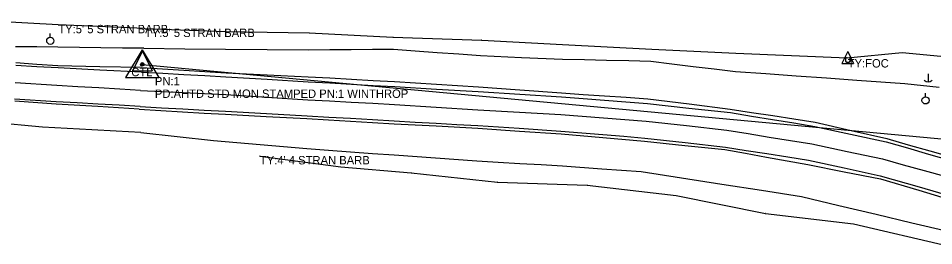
# Model space of a CAD drawing. Extents: x 592653 to 596268, y 1744647 to 1746025.
# Drawn here: x 593199 to 593746, y 1745827 to 1745963 of the extents above; entities that cross this region are included whole.
import ezdxf

# ---------------------------------------------------------------- set-up
doc = ezdxf.new("R2010")
doc.units = 0
for name, color, linetype in [('Default', 7, 'Continuous'), ('S_CAL_CORNER', 7, 'Continuous'), ('S_DITCHLINE', 7, 'Continuous'), ('S_EDGE_PAVEMENT', 7, 'Continuous'), ('S_FENCE', 7, 'Continuous'), ('S_FENCE_ANNOT', 7, 'Continuous'), ('S_MSC_PT_SYM', 7, 'Continuous'), ('S_PAVEMENT_CROWN', 7, 'Continuous'), ('S_PRIMARY_CTL', 7, 'Continuous'), ('S_PRIMARY_CTL_ANNOT', 7, 'Continuous'), ('S_SHOULDER', 7, 'Continuous'), ('S_UTILITY_POLE', 7, 'Continuous'), ('S_UTILITY_POLE_ANNOT', 7, 'Continuous')]:
    doc.layers.add(name, color=color, linetype=linetype)

msp = doc.modelspace()

# ---------------------------------------------------------------- linework, layer by layer
at = {"layer": 'Default'}
msp.add_line((593273.37, 1745935.37), (593756.49, 1745890.31), dxfattribs=at)
at = {"layer": 'S_CAL_CORNER'}
for p, q in [((593273.46, 1745943.35), (593267.58, 1745931.53)), ((593273.46, 1745943.35), (593279.27, 1745931.53)), ((593267.58, 1745931.53), (593279.27, 1745931.53))]:
    msp.add_line(p, q, dxfattribs=at)
at = {"layer": 'S_DITCHLINE'}
for points in [[(593223.04, 1745945.61), (593210.37, 1745945.77), (593197.7, 1745945.94)], [(593274.32, 1745944.97), (593261.5, 1745945.13), (593248.68, 1745945.29), (593235.86, 1745945.45), (593223.04, 1745945.61)], [(593274.32, 1745944.97), (593298.68, 1745944.69), (593323.04, 1745944.4), (593347.86, 1745944.27), (593372.68, 1745944.14), (593385.33, 1745944.24), (593397.98, 1745944.33), (593410.63, 1745944.43), (593423.27, 1745944.52), (593436.26, 1745943.54), (593449.25, 1745942.55), (593462.23, 1745941.57), (593475.22, 1745940.58), (593499.66, 1745939.55), (593524.11, 1745938.53), (593537.27, 1745938.21), (593550.43, 1745937.9), (593563.58, 1745937.59), (593576.74, 1745937.28), (593589.39, 1745935.73), (593602.03, 1745934.19), (593614.67, 1745932.64), (593627.31, 1745931.1), (593645.43, 1745929.83), (593663.54, 1745928.55), (593681.66, 1745927.28), (593699.77, 1745926.01), (593714.01, 1745924.97), (593728.26, 1745923.93), (593748.84, 1745921.72)], [(593213.86, 1745897.88), (593201.1, 1745899.09), (593188.35, 1745900.29)], [(593272.53, 1745894.74), (593257.86, 1745895.53), (593243.19, 1745896.31), (593228.52, 1745897.1), (593213.86, 1745897.88)], [(593272.53, 1745894.74), (593294.16, 1745892.32), (593315.79, 1745889.9), (593329.71, 1745888.72), (593343.64, 1745887.54), (593357.56, 1745886.36), (593371.48, 1745885.18), (593384.53, 1745884.21), (593397.58, 1745883.24), (593410.63, 1745882.27), (593423.68, 1745881.3), (593448.35, 1745879.55), (593473.02, 1745877.81), (593485.79, 1745877.05), (593498.56, 1745876.3), (593511.33, 1745875.54), (593524.1, 1745874.78), (593547.53, 1745873.07), (593570.95, 1745871.35), (593595.05, 1745867.64), (593619.14, 1745863.92), (593642.89, 1745860.25), (593666.64, 1745856.57), (593688.92, 1745851.23), (593711.19, 1745845.89), (593732.61, 1745840.86), (593754.04, 1745835.83)]]:
    msp.add_lwpolyline(points, dxfattribs=at)
at = {"layer": 'S_EDGE_PAVEMENT'}
for points in [[(593223.1, 1745933.25), (593210.51, 1745933.97), (593197.92, 1745934.69)], [(593272.95, 1745930.7), (593248.02, 1745931.97), (593223.1, 1745933.25)], [(593272.95, 1745930.7), (593285.53, 1745930.03), (593298.11, 1745929.36), (593310.7, 1745928.69), (593323.28, 1745928.02), (593347.77, 1745926.53), (593372.26, 1745925.05), (593385.21, 1745924.32), (593398.16, 1745923.59), (593411.11, 1745922.86), (593424.06, 1745922.13), (593448.95, 1745920.64), (593473.84, 1745919.16), (593498.68, 1745917.6), (593523.53, 1745916.04), (593536.32, 1745915.02), (593549.11, 1745914), (593561.91, 1745912.98), (593574.7, 1745911.97), (593599.47, 1745909.29), (593624.24, 1745906.62), (593636.83, 1745904.55), (593649.43, 1745902.49), (593662.02, 1745900.43), (593674.62, 1745898.36), (593695.91, 1745893.73), (593717.2, 1745889.09), (593729.84, 1745885.47), (593742.48, 1745881.85), (593755.13, 1745878.23)], [(593221.91, 1745913.07), (593197.1, 1745914.61)], [(593272.1, 1745910.21), (593259.55, 1745910.93), (593247.01, 1745911.64), (593234.46, 1745912.35), (593221.91, 1745913.07)], [(593272.1, 1745910.21), (593284.84, 1745909.51), (593297.58, 1745908.8), (593310.32, 1745908.09), (593323.06, 1745907.38), (593347.37, 1745906.04), (593371.68, 1745904.69), (593384.67, 1745903.94), (593397.67, 1745903.19), (593410.67, 1745902.43), (593423.66, 1745901.68), (593436.15, 1745900.98), (593448.63, 1745900.27), (593461.12, 1745899.57), (593473.6, 1745898.87), (593498.3, 1745897.21), (593523.01, 1745895.56), (593535.58, 1745894.53), (593548.15, 1745893.5), (593560.72, 1745892.46), (593573.29, 1745891.43), (593597.32, 1745888.72), (593621.35, 1745886.01), (593633.72, 1745884.06), (593646.08, 1745882.1), (593658.45, 1745880.15), (593670.82, 1745878.19), (593692.18, 1745873.53), (593713.55, 1745868.86), (593736.79, 1745862.21), (593760.04, 1745855.57)]]:
    msp.add_lwpolyline(points, dxfattribs=at)
at = {"layer": 'S_FENCE'}
for p, q in [((593223.26, 1745958.93), (593151.46, 1745962.87)), ((593274.91, 1745956.71), (593223.26, 1745958.93)), ((593274.91, 1745956.71), (593322.8, 1745954.94)), ((593322.8, 1745954.94), (593373.02, 1745954.18)), ((593373.02, 1745954.18), (593422.8, 1745951.7)), ((593422.8, 1745951.7), (593475.88, 1745949.73)), ((593475.88, 1745949.73), (593524.1, 1745947.23)), ((593524.1, 1745947.23), (593577.36, 1745944.46)), ((593577.36, 1745944.46), (593627.49, 1745942.11)), ((593627.49, 1745942.11), (593693.85, 1745939.24)), ((593693.85, 1745939.24), (593726.74, 1745942.49)), ((593726.74, 1745942.49), (593766.83, 1745938.65)), ((593343.52, 1745880.68), (593391.82, 1745874.16)), ((593391.82, 1745874.16), (593433.76, 1745870.7)), ((593433.76, 1745870.7), (593485.22, 1745865.01)), ((593485.22, 1745865.01), (593538.81, 1745863.36)), ((593538.81, 1745863.36), (593591.91, 1745857.11)), ((593591.91, 1745857.11), (593645.14, 1745846.3)), ((593645.14, 1745846.3), (593697.66, 1745840.19)), ((593697.66, 1745840.19), (593753.98, 1745827.15))]:
    msp.add_line(p, q, dxfattribs=at)
at = {"layer": 'S_MSC_PT_SYM'}
for points in [[(593223.26, 1745958.93), (593223.26, 1745958.98), (593223.26, 1745958.93), (593223.21, 1745958.93), (593223.26, 1745958.93), (593223.26, 1745958.88), (593223.26, 1745958.93), (593223.31, 1745958.93)], [(593274.91, 1745956.71), (593274.91, 1745956.76), (593274.91, 1745956.71), (593274.86, 1745956.71), (593274.91, 1745956.71), (593274.91, 1745956.66), (593274.91, 1745956.71), (593274.96, 1745956.71)], [(593322.8, 1745954.94), (593322.8, 1745954.99), (593322.8, 1745954.94), (593322.75, 1745954.94), (593322.8, 1745954.94), (593322.8, 1745954.89), (593322.8, 1745954.94), (593322.85, 1745954.94)], [(593373.02, 1745954.18), (593373.02, 1745954.23), (593373.02, 1745954.18), (593372.97, 1745954.18), (593373.02, 1745954.18), (593373.02, 1745954.13), (593373.02, 1745954.18), (593373.07, 1745954.18)], [(593422.8, 1745951.7), (593422.8, 1745951.75), (593422.8, 1745951.7), (593422.75, 1745951.7), (593422.8, 1745951.7), (593422.8, 1745951.65), (593422.8, 1745951.7), (593422.85, 1745951.7)], [(593475.88, 1745949.73), (593475.88, 1745949.78), (593475.88, 1745949.73), (593475.83, 1745949.73), (593475.88, 1745949.73), (593475.88, 1745949.68), (593475.88, 1745949.73), (593475.93, 1745949.73)], [(593524.1, 1745947.23), (593524.1, 1745947.28), (593524.1, 1745947.23), (593524.05, 1745947.23), (593524.1, 1745947.23), (593524.1, 1745947.18), (593524.1, 1745947.23), (593524.15, 1745947.23)], [(593577.36, 1745944.46), (593577.36, 1745944.51), (593577.36, 1745944.46), (593577.31, 1745944.46), (593577.36, 1745944.46), (593577.36, 1745944.41), (593577.36, 1745944.46), (593577.41, 1745944.46)], [(593627.49, 1745942.11), (593627.49, 1745942.16), (593627.49, 1745942.11), (593627.44, 1745942.11), (593627.49, 1745942.11), (593627.49, 1745942.06), (593627.49, 1745942.11), (593627.54, 1745942.11)], [(593726.74, 1745942.49), (593726.74, 1745942.54), (593726.74, 1745942.49), (593726.69, 1745942.49), (593726.74, 1745942.49), (593726.74, 1745942.44), (593726.74, 1745942.49), (593726.79, 1745942.49)], [(593693.85, 1745939.24), (593693.85, 1745939.29), (593693.85, 1745939.24), (593693.8, 1745939.24), (593693.85, 1745939.24), (593693.85, 1745939.19), (593693.85, 1745939.24), (593693.9, 1745939.24)], [(593343.52, 1745880.68), (593343.52, 1745880.73), (593343.52, 1745880.68), (593343.47, 1745880.68), (593343.52, 1745880.68), (593343.52, 1745880.63), (593343.52, 1745880.68), (593343.57, 1745880.68)], [(593391.82, 1745874.16), (593391.82, 1745874.21), (593391.82, 1745874.16), (593391.77, 1745874.16), (593391.82, 1745874.16), (593391.82, 1745874.11), (593391.82, 1745874.16), (593391.87, 1745874.16)], [(593433.76, 1745870.7), (593433.76, 1745870.75), (593433.76, 1745870.7), (593433.71, 1745870.7), (593433.76, 1745870.7), (593433.76, 1745870.65), (593433.76, 1745870.7), (593433.81, 1745870.7)], [(593485.22, 1745865.01), (593485.22, 1745865.06), (593485.22, 1745865.01), (593485.17, 1745865.01), (593485.22, 1745865.01), (593485.22, 1745864.96), (593485.22, 1745865.01), (593485.27, 1745865.01)], [(593538.81, 1745863.36), (593538.81, 1745863.41), (593538.81, 1745863.36), (593538.76, 1745863.36), (593538.81, 1745863.36), (593538.81, 1745863.31), (593538.81, 1745863.36), (593538.86, 1745863.36)], [(593591.91, 1745857.11), (593591.91, 1745857.16), (593591.91, 1745857.11), (593591.86, 1745857.11), (593591.91, 1745857.11), (593591.91, 1745857.06), (593591.91, 1745857.11), (593591.96, 1745857.11)], [(593645.14, 1745846.3), (593645.14, 1745846.35), (593645.14, 1745846.3), (593645.09, 1745846.3), (593645.14, 1745846.3), (593645.14, 1745846.25), (593645.14, 1745846.3), (593645.19, 1745846.3)], [(593697.66, 1745840.19), (593697.66, 1745840.24), (593697.66, 1745840.19), (593697.61, 1745840.19), (593697.66, 1745840.19), (593697.66, 1745840.14), (593697.66, 1745840.19), (593697.71, 1745840.19)]]:
    msp.add_lwpolyline(points, dxfattribs=at)
at = {"layer": 'S_PAVEMENT_CROWN'}
for points in [[(593222.38, 1745922.77), (593197.56, 1745924.28)], [(593272.36, 1745919.83), (593259.87, 1745920.56), (593247.37, 1745921.3), (593234.88, 1745922.03), (593222.38, 1745922.77)], [(593272.36, 1745919.83), (593285.06, 1745919.21), (593297.76, 1745918.6), (593310.46, 1745917.99), (593323.15, 1745917.38), (593347.61, 1745915.83), (593372.07, 1745914.29), (593384.99, 1745913.59), (593397.91, 1745912.89), (593410.83, 1745912.19), (593423.75, 1745911.48), (593448.68, 1745909.9), (593473.6, 1745908.33), (593498.37, 1745906.93), (593523.14, 1745905.54), (593535.86, 1745904.53), (593548.57, 1745903.53), (593561.29, 1745902.52), (593574, 1745901.51), (593598.05, 1745898.81), (593622.11, 1745896.11), (593634.77, 1745894.07), (593647.44, 1745892.02), (593660.11, 1745889.98), (593672.77, 1745887.94), (593693.86, 1745883.42), (593714.94, 1745878.91), (593727.36, 1745875.5), (593739.78, 1745872.08), (593752.2, 1745868.67)]]:
    msp.add_lwpolyline(points, dxfattribs=at)
at = {"layer": 'S_PRIMARY_CTL'}
for p, q in [((593273.37, 1745944.07), (593263.34, 1745927.55)), ((593273.37, 1745944.07), (593263.34, 1745927.55)), ((593273.37, 1745944.07), (593283.19, 1745927.55)), ((593273.37, 1745944.07), (593283.19, 1745927.55)), ((593263.34, 1745927.55), (593283.19, 1745927.55)), ((593263.34, 1745927.55), (593283.19, 1745927.55))]:
    msp.add_line(p, q, dxfattribs=at)
for radius in [1.04, 1.04, 0.609, 0.609, 0.344, 0.344]:
    msp.add_circle((593273.37, 1745935.37), radius, dxfattribs=at)
at = {"layer": 'S_SHOULDER'}
for points in [[(593223.02, 1745934.5), (593210.42, 1745935.35), (593197.82, 1745936.2)], [(593272.84, 1745933.47), (593247.93, 1745933.98), (593223.02, 1745934.5)], [(593272.84, 1745933.47), (593285.46, 1745932.71), (593298.08, 1745931.95), (593310.69, 1745931.18), (593323.31, 1745930.42), (593347.83, 1745929.21), (593372.35, 1745928), (593385.25, 1745927.28), (593398.14, 1745926.56), (593411.04, 1745925.83), (593423.94, 1745925.11), (593436.44, 1745924.31), (593448.94, 1745923.52), (593461.44, 1745922.72), (593473.94, 1745921.92), (593498.7, 1745920.13), (593523.45, 1745918.34), (593536.33, 1745917.47), (593549.21, 1745916.59), (593562.1, 1745915.72), (593574.98, 1745914.85), (593599.59, 1745911.76), (593624.2, 1745908.67), (593636.86, 1745906.72), (593649.52, 1745904.77), (593662.18, 1745902.82), (593674.84, 1745900.88), (593696.23, 1745895.98), (593717.62, 1745891.08), (593730.4, 1745887.44), (593743.17, 1745883.79), (593755.94, 1745880.14)], [(593221.99, 1745911.68), (593197.4, 1745913.32)], [(593271.56, 1745908.65), (593246.78, 1745910.17), (593221.99, 1745911.68)], [(593271.56, 1745908.65), (593284.43, 1745907.88), (593297.31, 1745907.11), (593310.18, 1745906.33), (593323.05, 1745905.56), (593347.28, 1745904.27), (593371.51, 1745902.99), (593384.56, 1745902.23), (593397.62, 1745901.46), (593410.68, 1745900.7), (593423.74, 1745899.94), (593448.63, 1745898.6), (593473.52, 1745897.27), (593498.41, 1745895.55), (593523.3, 1745893.82), (593548.19, 1745891.66), (593573.08, 1745889.51), (593597, 1745887.03), (593620.92, 1745884.56), (593633.31, 1745882.31), (593645.7, 1745880.06), (593658.08, 1745877.81), (593670.47, 1745875.56), (593692.17, 1745871.33), (593713.86, 1745867.1), (593736.68, 1745860.22), (593759.5, 1745853.33)]]:
    msp.add_lwpolyline(points, dxfattribs=at)
at = {"layer": 'S_UTILITY_POLE'}
for p, q in [((593218.33, 1745951.6), (593218.33, 1745953.71)), ((593694.26, 1745943.04), (593690.74, 1745935.95)), ((593694.26, 1745943.04), (593697.75, 1745935.95)), ((593690.74, 1745935.95), (593697.75, 1745935.95)), ((593693.06, 1745937.19), (593693.06, 1745939.63)), ((593693.68, 1745936.53), (593693.06, 1745937.19)), ((593694.88, 1745936.53), (593693.68, 1745936.53)), ((593695.43, 1745937.19), (593694.88, 1745936.53)), ((593695.43, 1745939.63), (593695.43, 1745937.19)), ((593742.24, 1745929.68), (593742.24, 1745924.95)), ((593740.57, 1745916.02), (593740.57, 1745918.13))]:
    msp.add_line(p, q, dxfattribs=at)
for centre in [(593218.46, 1745949.46), (593740.69, 1745913.88)]:
    msp.add_circle(centre, 2.13, dxfattribs=at)
msp.add_arc((593742.3, 1745928.38), 3.41, 226.3972, 313.6028, dxfattribs=at)

# ---------------------------------------------------------------- texts
at = {"layer": 'S_FENCE_ANNOT'}
for s, p in [("TY:5' 5 STRAN BARB", (593223.26, 1745953.93)), ("TY:5' 5 STRAN BARB", (593274.91, 1745951.71)), ("TY:4' 4 STRAN BARB", (593343.52, 1745875.68))]:
    msp.add_text(s, height=5, dxfattribs=at).set_placement(p)
at = {"layer": 'S_PRIMARY_CTL'}
msp.add_text('CTL', height=5, rotation=360, dxfattribs=at).set_placement((593266.78, 1745928.29))
msp.add_text('CTL', height=5, rotation=360, dxfattribs=at).set_placement((593266.78, 1745928.29))
at = {"layer": 'S_PRIMARY_CTL_ANNOT'}
for s, p in [('PN:1', (593280.87, 1745922.87)), ('PD:AHTD STD MON STAMPED PN:1 WINTHROP', (593280.87, 1745915.37))]:
    msp.add_text(s, height=5, dxfattribs=at).set_placement(p)
at = {"layer": 'S_UTILITY_POLE_ANNOT'}
msp.add_text('TY:FOC', height=5, dxfattribs=at).set_placement((593694.26, 1745933.51))

doc.saveas('drawing.dxf')
